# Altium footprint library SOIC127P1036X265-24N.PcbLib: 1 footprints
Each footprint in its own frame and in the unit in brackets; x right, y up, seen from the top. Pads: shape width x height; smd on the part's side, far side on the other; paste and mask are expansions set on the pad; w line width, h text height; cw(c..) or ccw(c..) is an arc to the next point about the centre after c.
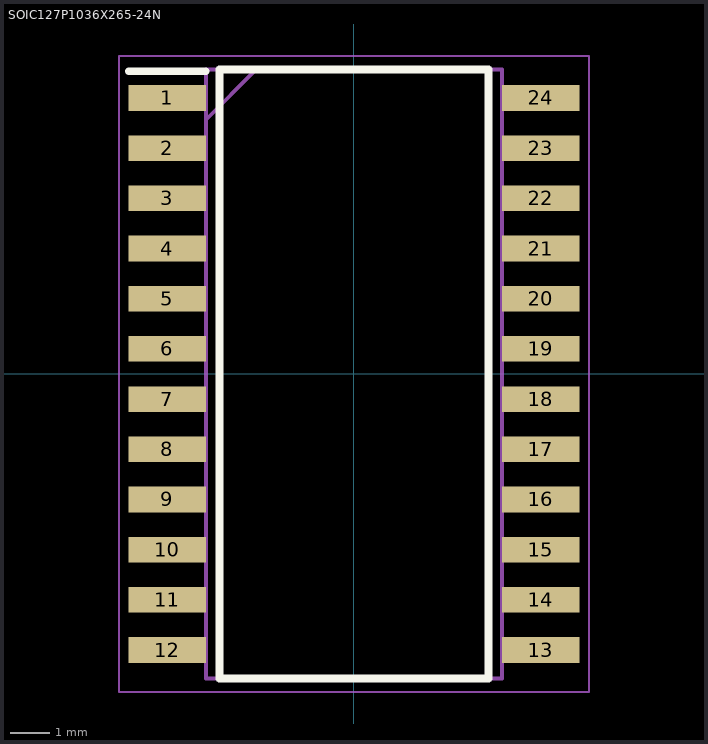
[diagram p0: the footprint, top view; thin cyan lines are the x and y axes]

## SOIC127P1036X265-24N [mm]
pads (24):
  rect 1.95x0.65 smd: 1(-4.725,6.985) 2(-4.725,5.715) 3(-4.725,4.445) 4(-4.725,3.175) 5(-4.725,1.905) 6(-4.725,0.635) 7(-4.725,-0.635) 8(-4.725,-1.905) 9(-4.725,-3.175) 10(-4.725,-4.445) 11(-4.725,-5.715) 12(-4.725,-6.985) 13(4.725,-6.985) 14(4.725,-5.715) 15(4.725,-4.445) 16(4.725,-3.175) 17(4.725,-1.905) 18(4.725,-0.635) 19(4.725,0.635) 20(4.725,1.905) 21(4.725,3.175) 22(4.725,4.445) 23(4.725,5.715) 24(4.725,6.985)
Top Overlay:
  lines w0.2: -5.7,7.66 -3.75,7.66 ; -3.4,-7.7 3.4,-7.7 3.4,7.7 -3.4,7.7 -3.4,-7.7
Mechanical 15:
  lines w0.1: -3.75,6.43 -2.48,7.7 ; -3.75,-7.7 3.75,-7.7 3.75,7.7 -3.75,7.7 -3.75,-7.7
Mechanical 20:
  lines w0.05: -5.95,-8.05 5.95,-8.05 5.95,8.05 -5.95,8.05 -5.95,-8.05
3D body "IS31FL3218-GRLS2.stp": height 5.8, standoff -4.65, extent -10,-3.376 10,3.376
